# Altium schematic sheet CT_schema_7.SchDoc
size 385 x 301 mm
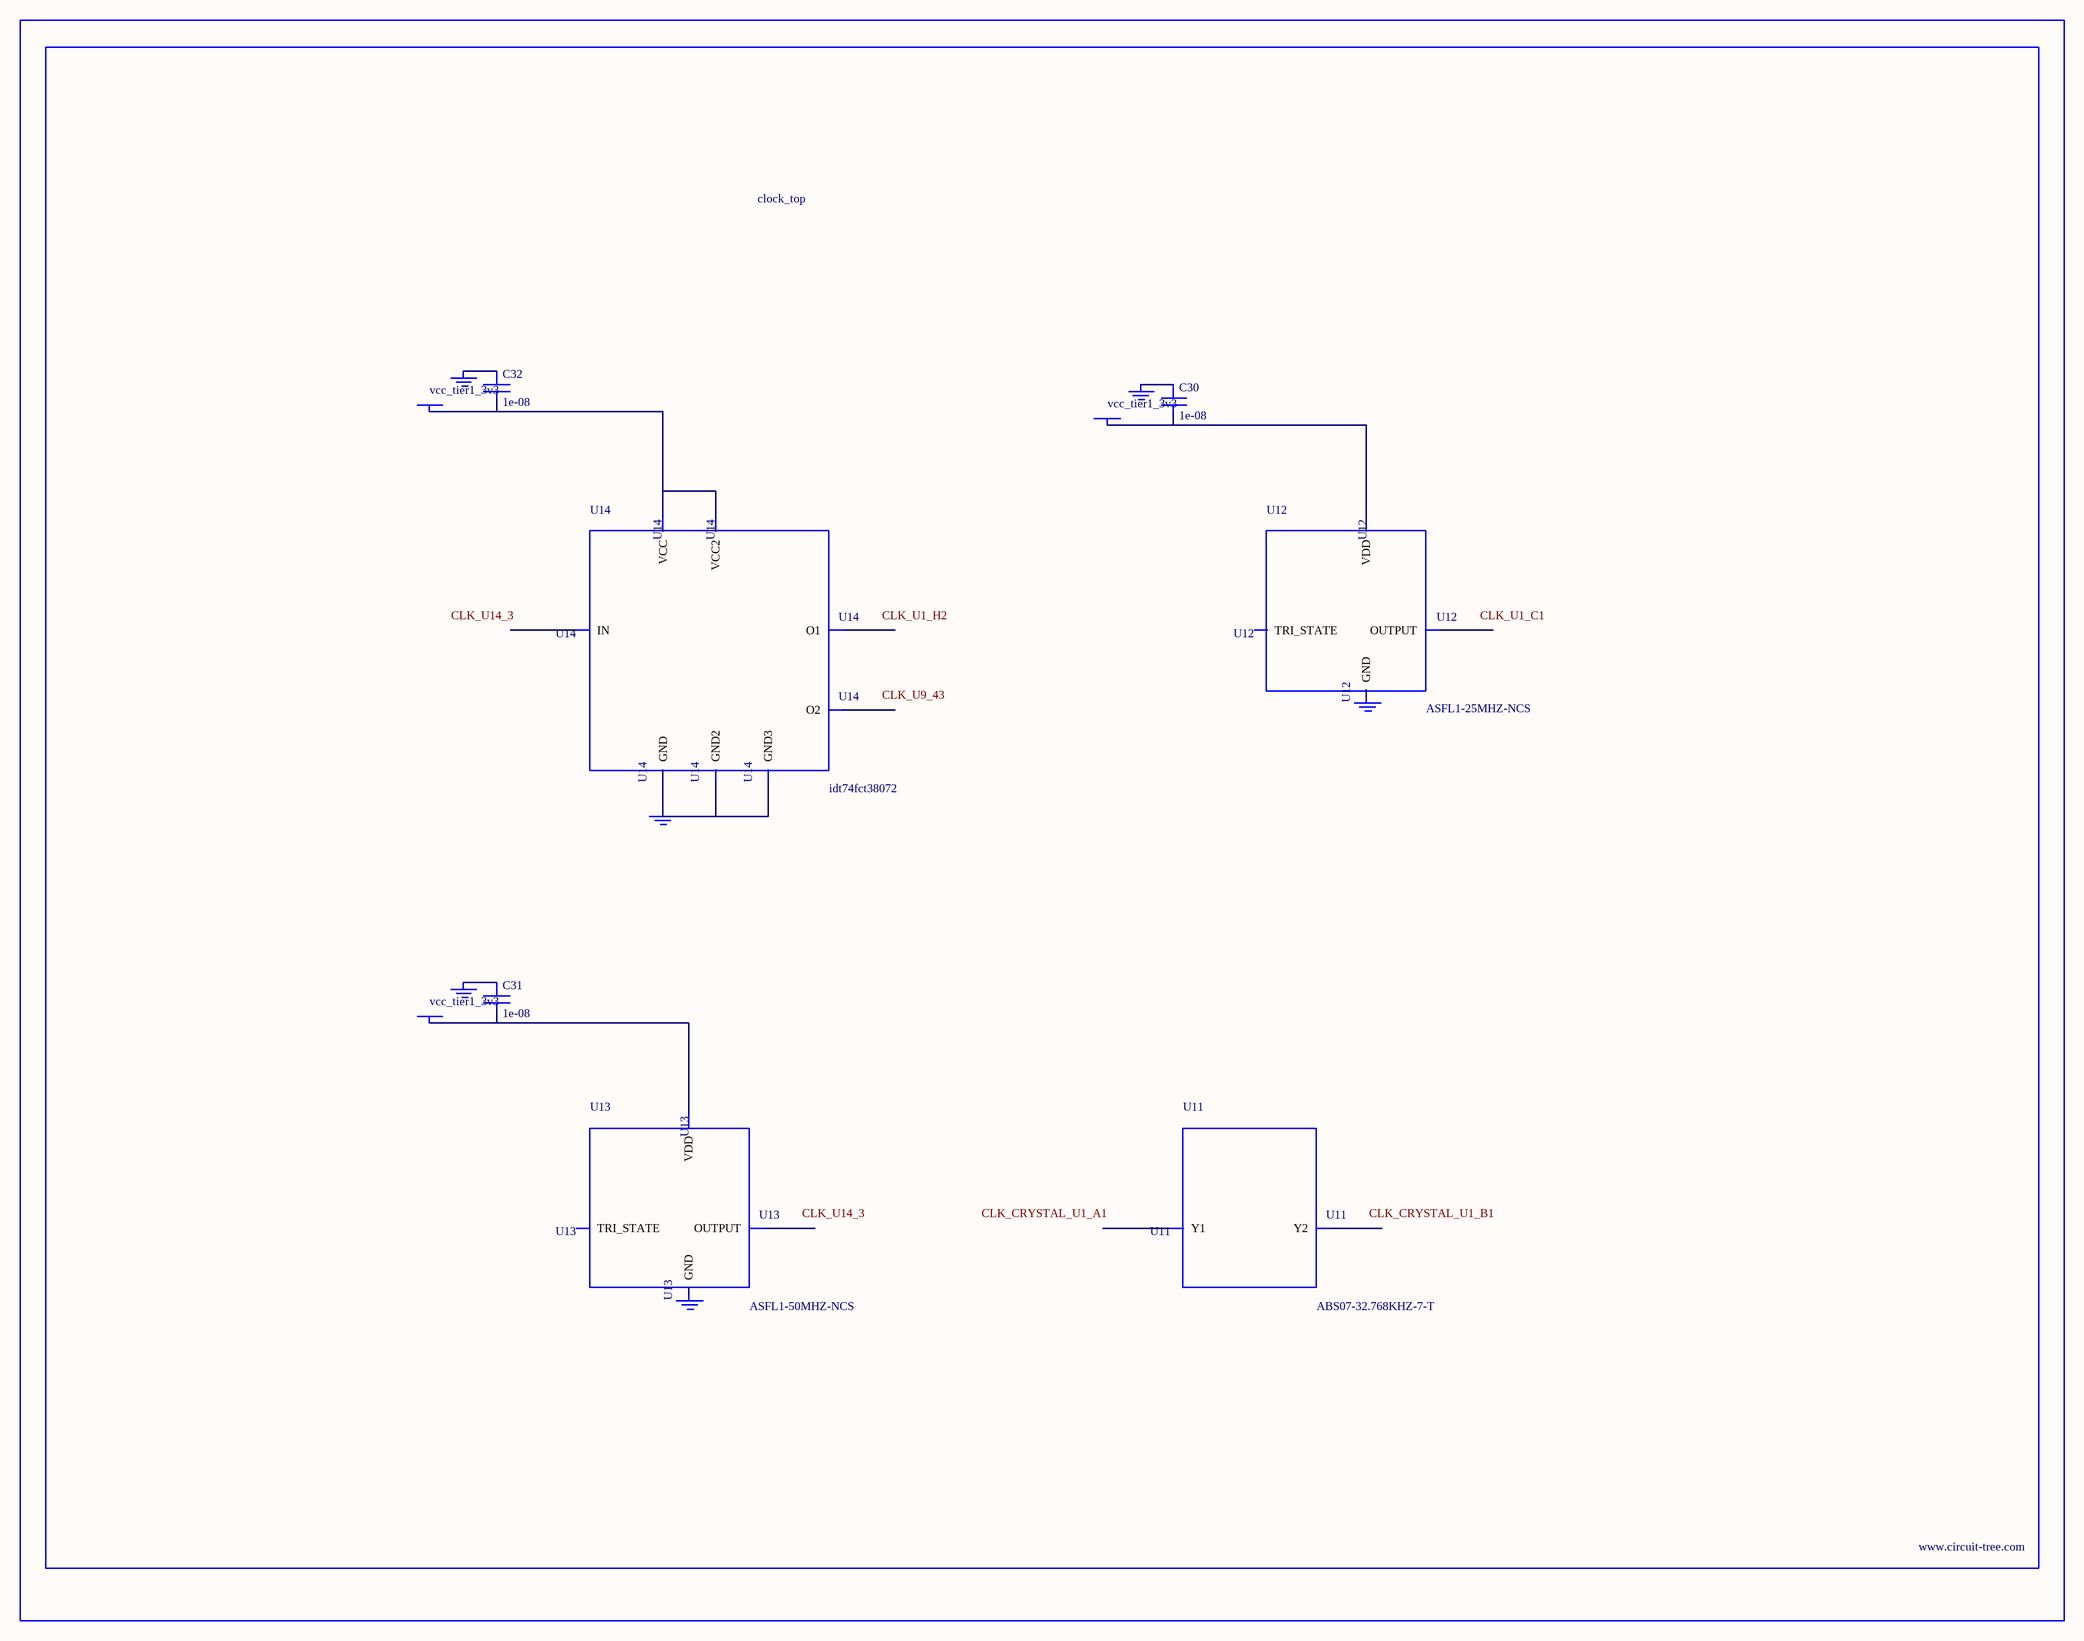
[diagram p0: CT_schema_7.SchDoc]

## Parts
BORDER6  (no value)
C30  1e-08  [C0402]
C31  1e-08  [C0402]
C32  1e-08  [C0402]
GND_INSTANCE_6_0  (no value)
GND_INSTANCE_6_1  (no value)
GND_INSTANCE_6_2  (no value)
GND_INSTANCE_6_3  (no value)
GND_INSTANCE_6_4  (no value)
GND_INSTANCE_6_5  (no value)
POWER_INSTANCE_6_0  vcc_tier1_3v3
POWER_INSTANCE_6_1  vcc_tier1_3v3
POWER_INSTANCE_6_2  vcc_tier1_3v3
U11  ABS07-32.768KHZ-7-T  [ABS07-32.768KHZ-7-T]
U12  ASFL1-25MHZ-NCS  [ASFL1]
U13  ASFL1-50MHZ-NCS  [ASFL1]
U14  idt74fct38072  [IDT74FCT38072]

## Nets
NetC30_1: C30.1 GND_INSTANCE_6_0.0(GND)
NetC30_2: C30.2 POWER_INSTANCE_6_0.0(PWR) U12.4(VDD)
NetC31_1: C31.1 GND_INSTANCE_6_2.0(GND)
NetC31_2: C31.2 POWER_INSTANCE_6_1.0(PWR) U13.4(VDD)
NetC32_1: C32.1 GND_INSTANCE_6_4.0(GND)
NetC32_2: C32.2 POWER_INSTANCE_6_2.0(PWR) U14.1(VCC) U14.2(VCC2)
NetGND_INSTANCE_6_5_0: GND_INSTANCE_6_5.0(GND) U14.4(GND) U14.5(GND2) U14.8(GND3)

Not connected (* = marked no-connect by the designer): GND_INSTANCE_6_1 0(GND); GND_INSTANCE_6_3 0(GND); U11 1(Y1) 2(Y2); U12 1(TRI_STATE) 2(GND) 3(OUTPUT); U13 1(TRI_STATE) 2(GND) 3(OUTPUT); U14 3(IN) 6(O2) 7(O1)

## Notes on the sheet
- Labels drawn without touching a wire or pin: CLK_CRYSTAL_U1_A1, CLK_CRYSTAL_U1_B1, CLK_U1_C1, CLK_U1_H2, CLK_U9_43, CLK_U14_3

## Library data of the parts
BORDER6 = BORDER_PAGE6
C30-C32 = C0402C103K3RAC
GND_INSTANCE_6_0-GND_INSTANCE_6_5 = GND
POWER_INSTANCE_6_0-POWER_INSTANCE_6_2 = PWR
